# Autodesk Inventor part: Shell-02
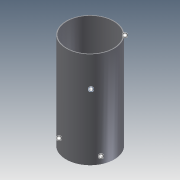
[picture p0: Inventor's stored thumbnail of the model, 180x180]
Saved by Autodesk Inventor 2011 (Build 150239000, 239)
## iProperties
Created: 2010-06
Part Number: Shell-02
Document SubType Name: Modeling
Designer: mklassen
Density: 1 g/cm^3
OD: 36.000 in
THK: 0.625 in
LEN: 6.000 ft
SKVOFS: 6.000 in
Author: mklassen
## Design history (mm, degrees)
sketch "skShell"
  geometry: C1 r 457.2 at (0, 0); C2 r 441.325 at (0, 0); 1 further point
  constraints: 2 centre point, 1 coincident
  dimensions: "d0" = 914.4 diameter of C1 (derived); "d1" = 15.875 radial gap between concentric circles of C2 C1 (derived)
extrude "Shell" new body sketch "skShell" stored distance "d2" = 1828.8 (derived); taper "d3" = 0 deg
body "Solid1"
other parameters: "d4" = 0, "d5" = 0, "d6" = 0, "d8" = 0, "SKVOFS" = 152.4 [user parameter], "d9" = 0
